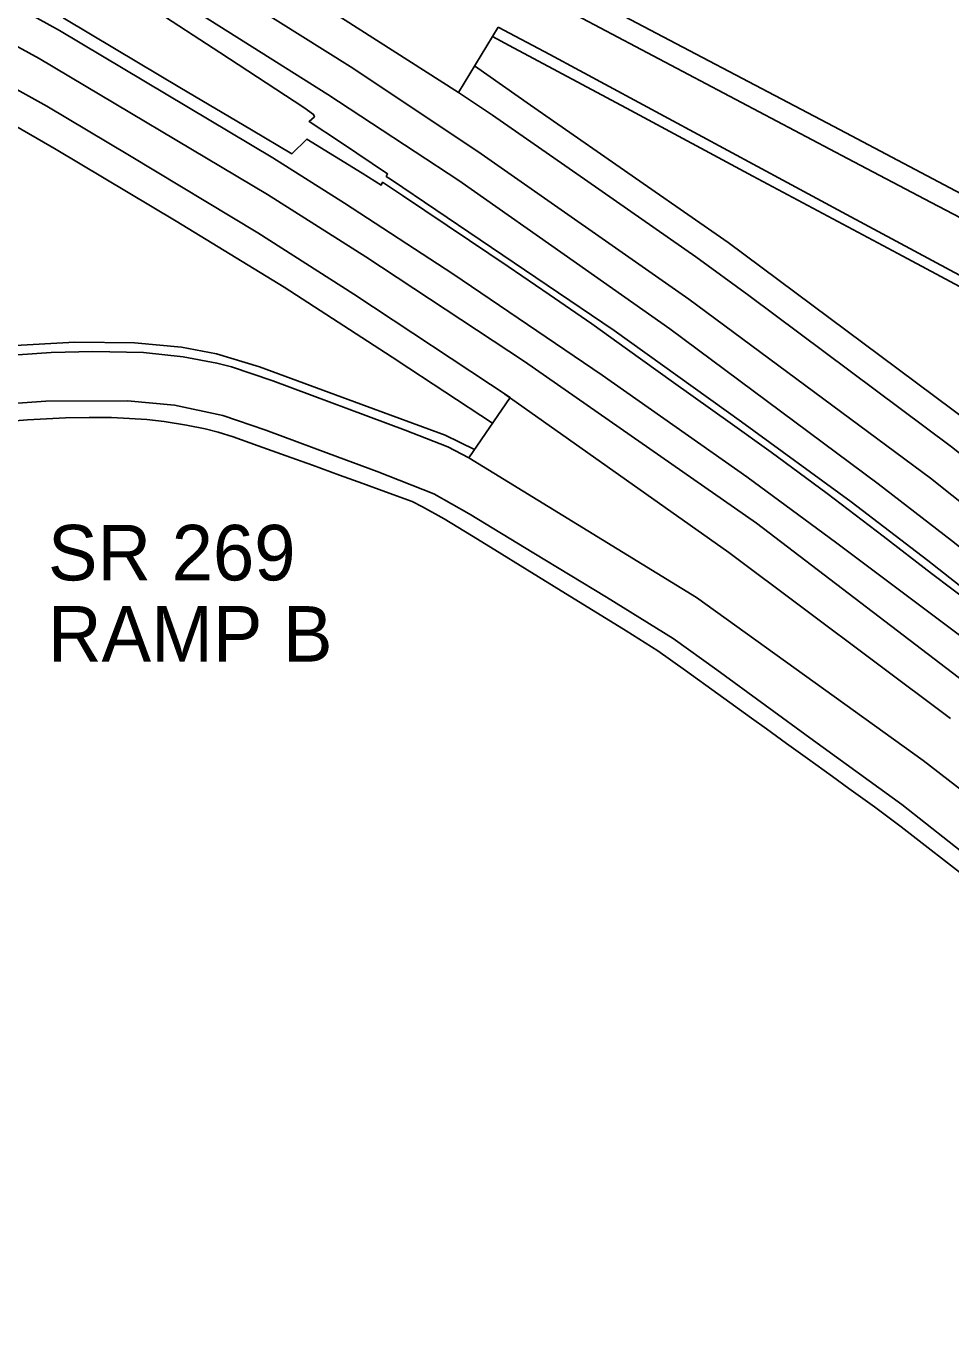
# Model space of a CAD drawing. Extents: x 1855721 to 1876784, y 662259 to 674089.
# Drawn here: x 1874925 to 1875224.8, y 669382.3 to 669810.1 of the extents above; entities that cross this region are included whole.
import ezdxf

# ---------------------------------------------------------------- set-up
doc = ezdxf.new("R2010")
doc.units = 0
for name, color, linetype in [('_CIVIL_CONSTRUCTION', 7, 'Continuous'), ('GE_X_Alignment_100_Bearings', 7, 'Continuous'), ('GE_X_Alignment_100_Cardinal_Points', 7, 'Continuous'), ('GE_X_Alignment_100_Curve_Data', 7, 'Continuous'), ('SC_Scratch1', 7, 'Continuous')]:
    doc.layers.add(name, color=color, linetype=linetype)

msp = doc.modelspace()

# ---------------------------------------------------------------- linework, layer by layer
at = {"layer": '_CIVIL_CONSTRUCTION'}
for p, q in [((1875078.08, 669809.9), (1875065.16, 669788.67)), ((1875068.54, 669670.25), (1875081.95, 669689.73))]:
    msp.add_line(p, q, dxfattribs=at)
for points in [[(1874641.2, 670039.89), (1874701.25, 670015), (1874731.67, 670001.32), (1874782.75, 669977.61), (1874811.12, 669963.54), (1874871.31, 669933.45), (1874894.26, 669921.88), (1874992.84, 669871.11), (1875067.06, 669832.68), (1875105.4, 669812.63), (1875191.41, 669767.29), (1875218.5, 669753.05), (1875275.82, 669723.07), (1875323.45, 669698.25), (1875375.21, 669671.09), (1875430.91, 669641.84), (1875462.7, 669625.07)], [(1875081.95, 669689.73), (1875031.29, 669723.23), (1875000.09, 669743.15), (1874958.45, 669768.21), (1874931.68, 669784.23), (1874893.05, 669805.7), (1874839.95, 669834.6), (1874820.66, 669844.52), (1874755.1, 669878.1), (1874738.01, 669886.1), (1874675.19, 669914.89), (1874656.55, 669923.15), (1874616.51, 669940.01)], [(1875065.16, 669788.67), (1875076.19, 669781.3), (1875107.16, 669759.82), (1875142.19, 669735.44), (1875159.36, 669722.88), (1875225.15, 669673.79), (1875288.74, 669623.24), (1875307.09, 669608.4), (1875347.56, 669573.81), (1875367.42, 669556.3), (1875382.63, 669542.62), (1875406.01, 669521.36), (1875469.59, 669460.89)], [(1874913.09, 669687.29), (1874931.35, 669688.57), (1874957.79, 669688.72), (1874973.11, 669687.24), (1874988.75, 669683.92), (1875002.72, 669679.13), (1875023.07, 669671.61), (1875038.86, 669665.78), (1875057.24, 669658.5), (1875068.64, 669652.09), (1875089.68, 669639.3), (1875113.16, 669625.03), (1875134.86, 669611.66), (1875148.96, 669601.42), (1875180.4, 669578.6), (1875208.96, 669557.77), (1875239.7, 669533.58)]]:
    msp.add_lwpolyline(points, dxfattribs=at)
at = {"layer": 'GE_X_Alignment_100_Bearings'}
for points in [[(1873917.88, 670211.07), (1874033.57, 670192.38), (1874128.97, 670172.77), (1874226.34, 670149.67), (1874324.56, 670121.94), (1874380.21, 670105.03), (1874464.42, 670075.97), (1874542.9, 670046.78), (1874613.26, 670018), (1874690.49, 669983.78), (1874745.1, 669957.92), (1874833.48, 669912.76), (1874913.16, 669868.6), (1874975.02, 669831.72), (1875030.09, 669797.13), (1875071.49, 669769.59), (1875139.95, 669721.68), (1875218.25, 669663.57), (1875295.5, 669602.11), (1875347.35, 669557.96), (1875393.18, 669516.35), (1875460.82, 669452.24)], [(1873940.99, 670131.62), (1874033.62, 670118.26), (1874131.15, 670100.65), (1874186.92, 670088.55), (1874278.59, 670066.55), (1874368.65, 670041.87), (1874427.9, 670023.25), (1874517.06, 669991.96), (1874605.73, 669957.51), (1874668.58, 669931.07), (1874758.04, 669889.96), (1874843.89, 669846.49), (1874929.24, 669799.74), (1875003.27, 669755.58), (1875035.18, 669735.37), (1875086.58, 669701.41), (1875161.85, 669649.01), (1875231.41, 669595.91), (1875301.33, 669539.99), (1875372.37, 669478.94), (1875442.56, 669414.34), (1875474.84, 669382.32)]]:
    msp.add_lwpolyline(points, dxfattribs=at)
at = {"layer": 'GE_X_Alignment_100_Cardinal_Points'}
for p, q in [((1875080.23, 669690.87), (1875152.89, 669639.49)), ((1875068.54, 669670.25), (1875142.4, 669624.97)), ((1875152.89, 669639.49), (1875224.83, 669585.65)), ((1875142.4, 669624.97), (1875215.91, 669572.08)), ((1875215.91, 669572.08), (1875282.55, 669520.21))]:
    msp.add_line(p, q, dxfattribs=at)
msp.add_lwpolyline([(1875065.16, 669788.67), (1874980.37, 669842.99), (1874920.22, 669878.89), (1874838.17, 669924.24), (1874750.3, 669969.21), (1874696.17, 669994.83)], dxfattribs=at)
at = {"layer": 'GE_X_Alignment_100_Curve_Data'}
for points in [[(1875464.77, 669431.52), (1875445.32, 669450.65), (1875388.95, 669504.59), (1875372.59, 669519.6), (1875348.68, 669541.23), (1875336.32, 669552.21), (1875292.12, 669589.82), (1875272.97, 669605.32), (1875225.14, 669643.42), (1875201.38, 669661.81), (1875133.79, 669712.05), (1875103.44, 669733.35), (1875065.27, 669760.11), (1875022.83, 669788.08), (1874968.77, 669822.14), (1874930.2, 669845.19), (1874906.07, 669859.59), (1874847.1, 669892.21), (1874824.18, 669904.74), (1874746.86, 669944.15), (1874730.64, 669952.1), (1874689.99, 669971.59), (1874670.21, 669980.46), (1874619.85, 670002.65)], [(1874625.43, 669961.44), (1874654.09, 669949.3), (1874703.09, 669927.51), (1874738.06, 669911.52), (1874773.65, 669894.72), (1874846.89, 669857.73), (1874874.88, 669842.42), (1874908.64, 669823.81), (1874935.76, 669808.82), (1875004.95, 669767.53), (1875028.23, 669752.82), (1875063.4, 669729.88), (1875111.79, 669697.05), (1875158.76, 669664.02), (1875187.96, 669642.57), (1875238.94, 669604.31), (1875294.54, 669559.52), (1875314.39, 669543.2), (1875365.63, 669499.22), (1875401.6, 669467.18), (1875442.31, 669430.05), (1875463.95, 669409.25)], [(1875874.25, 669469.79), (1875840.43, 669469.9), (1875779.14, 669475.89), (1875713.62, 669490.78), (1875655.84, 669510.33), (1875647.79, 669513.55), (1875592.18, 669538.55), (1875535.37, 669567.48), (1875514.39, 669578.29), (1875430.92, 669621.83), (1875358.6, 669659.85), (1875317.3, 669681.6), (1875276.64, 669703.19), (1875234.97, 669725.55), (1875191.02, 669749.16), (1875094.85, 669800.97), (1875078.08, 669809.9)], [(1874916.03, 669703.21), (1874933.09, 669704.32), (1874946.61, 669704.74), (1874963.03, 669704.33), (1874975.86, 669703), (1874986.84, 669700.92), (1874991.55, 669699.72), (1875004.95, 669695.16), (1875047.92, 669679.17), (1875061.76, 669673.81), (1875068.54, 669670.25)]]:
    msp.add_lwpolyline(points, dxfattribs=at)
at = {"layer": 'SC_Scratch1'}
msp.add_line((1875045.32, 669701.8), (1875076.27, 669681.48), dxfattribs=at)
for points in [[(1874611.63, 670061.89), (1874649.03, 670046.73), (1874680.63, 670033.23), (1874718.74, 670016.77), (1874761.14, 669997.1), (1874787.39, 669984.92), (1874824.04, 669966.53), (1874866.09, 669945.33), (1874899.52, 669928.34), (1874996.66, 669877.63), (1875063.43, 669842.49), (1875112.41, 669816.75), (1875186.91, 669777.61), (1875230.31, 669754.74), (1875288.61, 669723.85), (1875288.97, 669724.16), (1875294.76, 669721.14), (1875305.58, 669715.45), (1875323.27, 669706.09), (1875337.75, 669698.45), (1875440.07, 669644.74), (1875467.01, 669630.39)], [(1874638.27, 669919.9), (1874663.63, 669909.02), (1874680.3, 669901.37), (1874718.77, 669883.71), (1874747.45, 669870.53), (1874785.88, 669851.07), (1874816.8, 669835.42), (1874837.05, 669825.05), (1874873.57, 669804.81), (1874902.23, 669788.93), (1874934.69, 669770.23), (1874973.67, 669746.95), (1875008.66, 669725.5), (1875045.5, 669701.69)], [(1874965.87, 669815.96), (1874987.78, 669801.64), (1875015.05, 669783.77), (1875018.19, 669781.58), (1875018.47, 669780.84), (1875016.72, 669779.29), (1875027.21, 669772.34), (1875042.18, 669762.29), (1875042.01, 669761.85), (1875041.76, 669761.48), (1875043.47, 669760.31), (1875072.23, 669740.88), (1875115.69, 669711.53), (1875157.02, 669681.93), (1875192.52, 669655.89), (1875217.47, 669636.95), (1875252.09, 669609.73)], [(1875231.83, 669622.71), (1875218.68, 669632.74), (1875202.91, 669644.76), (1875184.74, 669658.61), (1875166.63, 669672.02), (1875153.29, 669681.56), (1875134.99, 669694.66), (1875120.05, 669705.36), (1875108.49, 669713.63), (1875094.65, 669723.22), (1875081.3, 669732.21), (1875068.78, 669740.64), (1875047.01, 669755.27), (1875040.6, 669759.57), (1875040.14, 669758.67), (1875033.97, 669762.48), (1875016.01, 669773.57), (1875011.09, 669768.8), (1874998.1, 669776.52), (1874974.86, 669790.32), (1874954.11, 669802.65), (1874936.94, 669812.85)], [(1875875.31, 669466.58), (1875852.93, 669466.65), (1875840.14, 669466.69), (1875803.85, 669470.1), (1875778.6, 669472.47), (1875712.87, 669487.18), (1875651.77, 669508.17), (1875591.52, 669535.31), (1875522.54, 669570.13), (1875430.07, 669619.1), (1875356.57, 669657.41), (1875304.59, 669684.7), (1875260.24, 669708.36), (1875207.72, 669736.45), (1875160.72, 669761.59), (1875121.05, 669782.8), (1875081.65, 669803.88), (1875076.19, 669806.8)], [(1875070.42, 669797.31), (1875088.57, 669784.57), (1875126.48, 669758.21), (1875152.65, 669740), (1875201.84, 669703.39), (1875231.65, 669681.19), (1875280.3, 669642.36), (1875309.31, 669619.22), (1875331.64, 669600.39), (1875362.52, 669574.36), (1875408.66, 669532.72), (1875477.15, 669467.76)], [(1875070.36, 669672.89), (1875060.9, 669677.53), (1875035.54, 669686.89), (1875000.69, 669699.75), (1874986.66, 669703.94), (1874975.35, 669706.06), (1874960.07, 669707.54), (1874940.77, 669707.7), (1874919.47, 669706.48)], [(1874913.3, 669681.59), (1874925.42, 669682.56), (1874937.69, 669683.16), (1874945.4, 669683.31), (1874952.67, 669683.24), (1874958.47, 669683), (1874964.06, 669682.59), (1874969.69, 669681.98), (1874976.95, 669680.85), (1874983, 669679.58), (1874987.28, 669678.49), (1874992.11, 669677.03), (1875000.25, 669674.14), (1875009.26, 669670.88), (1875017.82, 669667.78), (1875026.65, 669664.59), (1875034.13, 669661.89), (1875041.57, 669659.2), (1875050.22, 669656.07), (1875053.58, 669654.32), (1875060.58, 669650.47), (1875069.47, 669644.98), (1875076.98, 669640.34), (1875087.49, 669633.85), (1875099.89, 669626.2), (1875110.27, 669619.79), (1875119.55, 669614.06), (1875129.89, 669607.65), (1875138.84, 669601.2), (1875149.31, 669593.66), (1875160.19, 669585.82), (1875165.1, 669582.29), (1875171.59, 669577.61), (1875178.4, 669572.71), (1875186.5, 669566.88), (1875191.86, 669563.02), (1875200.13, 669557.06), (1875208.78, 669550.55), (1875231.59, 669532.8)]]:
    msp.add_lwpolyline(points, dxfattribs=at)

# ---------------------------------------------------------------- texts
for s, p in [('SR 269', (1874932.05, 669630.46)), ('RAMP B', (1874932.05, 669604.13))]:
    msp.add_text(s, height=18, dxfattribs=at).set_placement(p)

doc.saveas('drawing.dxf')
